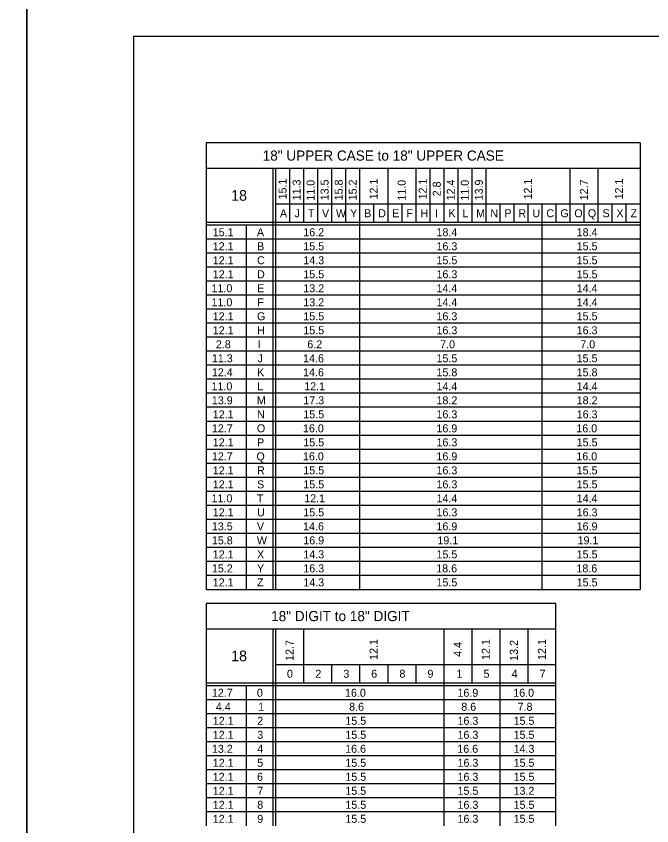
# Model space of a CAD drawing. Extents: x 637580 to 641849, y 297270 to 299646.
# Drawn here: x 640099.4 to 640337.4, y 298146.6 to 298450.1 of the extents above; entities that cross this region are included whole.
import ezdxf

# ---------------------------------------------------------------- set-up
doc = ezdxf.new("R2010")
doc.units = 0
for name, color, linetype in [('1', 7, 'Continuous'), ('2', 7, 'Continuous'), ('XCS-GRID-HVGL', 7, 'Continuous')]:
    doc.layers.add(name, color=color, linetype=linetype)

msp = doc.modelspace()

# ---------------------------------------------------------------- linework, layer by layer
at = {"layer": '1'}
for q in [(640929.31, 298442.63), (640143.31, 297878.63)]:
    msp.add_line((640143.31, 298442.63), q, dxfattribs=at)
at = {"layer": '2'}
for p, q in [((640333.01, 298402.63), (640170.51, 298402.63)), ((640170.51, 298402.63), (640170.51, 298235.25)), ((640333.01, 298402.63), (640333.01, 298235.25)), ((640170.51, 298393.13), (640333.01, 298393.13)), ((640195.51, 298393.13), (640195.51, 298235.25)), ((640196.51, 298393.13), (640196.51, 298235.25)), ((640201.76, 298393.13), (640201.76, 298372.75)), ((640207.01, 298393.13), (640207.01, 298372.75)), ((640212.26, 298393.13), (640212.26, 298372.75)), ((640217.51, 298393.13), (640217.51, 298372.75)), ((640222.76, 298393.13), (640222.76, 298372.75)), ((640228.01, 298393.13), (640228.01, 298235.25)), ((640238.51, 298393.13), (640238.51, 298372.75)), ((640249.01, 298393.13), (640249.01, 298372.75)), ((640254.26, 298393.13), (640254.26, 298372.75)), ((640259.51, 298393.13), (640259.51, 298372.75)), ((640264.76, 298393.13), (640264.76, 298372.75)), ((640270.01, 298393.13), (640270.01, 298372.75)), ((640275.26, 298393.13), (640275.26, 298372.75)), ((640306.76, 298393.13), (640306.76, 298372.75)), ((640317.26, 298393.13), (640317.26, 298372.75)), ((640196.51, 298379.75), (640333.01, 298379.75)), ((640233.26, 298379.75), (640233.26, 298372.75)), ((640243.76, 298379.75), (640243.76, 298372.75)), ((640280.51, 298379.75), (640280.51, 298372.75)), ((640285.76, 298379.75), (640285.76, 298372.75)), ((640291.01, 298379.75), (640291.01, 298372.75)), ((640291.01, 298379.75), (640291.01, 298372.75)), ((640296.26, 298379.75), (640296.26, 298235.25)), ((640301.51, 298379.75), (640301.51, 298372.75)), ((640312.01, 298379.75), (640312.01, 298372.75)), ((640322.51, 298379.75), (640322.51, 298372.75)), ((640327.76, 298379.75), (640327.76, 298372.75)), ((640333.01, 298372.75), (640170.51, 298372.75)), ((640333.01, 298371.75), (640170.51, 298371.75)), ((640185.51, 298371.75), (640185.51, 298235.25)), ((640333.01, 298366.5), (640170.51, 298366.5)), ((640333.01, 298361.25), (640170.51, 298361.25)), ((640333.01, 298356), (640170.51, 298356)), ((640333.01, 298350.75), (640170.51, 298350.75)), ((640333.01, 298345.5), (640170.51, 298345.5)), ((640333.01, 298340.25), (640170.51, 298340.25)), ((640333.01, 298335), (640170.51, 298335)), ((640333.01, 298329.75), (640170.51, 298329.75)), ((640333.01, 298324.5), (640170.51, 298324.5)), ((640333.01, 298319.25), (640170.51, 298319.25)), ((640333.01, 298314), (640170.51, 298314)), ((640333.01, 298308.75), (640170.51, 298308.75)), ((640333.01, 298303.5), (640170.51, 298303.5)), ((640333.01, 298298.25), (640170.51, 298298.25)), ((640333.01, 298293), (640170.51, 298293)), ((640333.01, 298287.75), (640170.51, 298287.75)), ((640333.01, 298282.5), (640170.51, 298282.5)), ((640333.01, 298277.25), (640170.51, 298277.25)), ((640333.01, 298272), (640170.51, 298272)), ((640333.01, 298266.75), (640170.51, 298266.75)), ((640333.01, 298261.5), (640170.51, 298261.5)), ((640333.01, 298256.25), (640170.51, 298256.25)), ((640333.01, 298251), (640170.51, 298251)), ((640333.01, 298245.75), (640170.51, 298245.75)), ((640333.01, 298240.5), (640170.51, 298240.5)), ((640170.51, 298235.25), (640170.51, 298235.25)), ((640170.51, 298235.25), (640333.01, 298235.25)), ((640301.51, 298230), (640170.51, 298230)), ((640170.51, 298230), (640170.51, 298146.63)), ((640301.51, 298146.63), (640301.51, 298230)), ((640170.51, 298220.5), (640301.51, 298220.5)), ((640195.51, 298220.5), (640195.51, 298146.63)), ((640196.51, 298220.5), (640196.51, 298146.63)), ((640207.01, 298220.5), (640207.01, 298200.13)), ((640259.51, 298220.5), (640259.51, 298146.63)), ((640270.01, 298220.5), (640270.01, 298200.13)), ((640280.51, 298220.5), (640280.51, 298146.63)), ((640291.01, 298220.5), (640291.01, 298200.13)), ((640196.51, 298207.13), (640301.51, 298207.13)), ((640217.51, 298207.13), (640217.51, 298200.13)), ((640228.01, 298207.13), (640228.01, 298200.13)), ((640238.51, 298207.13), (640238.51, 298200.13)), ((640249.01, 298207.13), (640249.01, 298200.13)), ((640301.51, 298200.13), (640170.51, 298200.13)), ((640301.51, 298199.13), (640170.51, 298199.13)), ((640185.51, 298199.13), (640185.51, 298146.63)), ((640301.51, 298193.88), (640170.51, 298193.88)), ((640301.51, 298188.63), (640170.51, 298188.63)), ((640301.51, 298183.38), (640170.51, 298183.38)), ((640301.51, 298178.13), (640170.51, 298178.13)), ((640301.51, 298172.88), (640170.51, 298172.88)), ((640301.51, 298167.63), (640170.51, 298167.63)), ((640301.51, 298162.38), (640170.51, 298162.38)), ((640301.51, 298157.13), (640170.51, 298157.13)), ((640301.51, 298151.88), (640170.51, 298151.88))]:
    msp.add_line(p, q, dxfattribs=at)
at = {"layer": 'XCS-GRID-HVGL'}
for points in [[(639262.31, 298457.63), (640103.31, 298457.63), (640103.31, 297863.63), (639262.31, 297863.63)], [(640103.31, 298457.63), (640944.31, 298457.63), (640944.31, 297863.63), (640103.31, 297863.63)]]:
    msp.add_lwpolyline(points, close=True, dxfattribs=at)

# ---------------------------------------------------------------- texts
at = {"layer": '2'}
for s, height, p in [('18" UPPER CASE to 18" UPPER CASE', 3.8, (640191.7, 298395.98)), ('18', 4, (640179.88, 298380.94)), ('A', 3, (640198.16, 298374.75)), ('J', 3, (640203.64, 298374.75)), ('T', 3, (640208.64, 298374.75)), ('V', 3, (640213.91, 298374.75)), ('W', 3, (640219.13, 298374.75)), ('Y', 3, (640224.44, 298374.75)), ('B', 3, (640229.7, 298374.75)), ('D', 3, (640234.95, 298374.75)), ('E', 3, (640240.22, 298374.75)), ('F', 3, (640245.52, 298374.75)), ('H', 3, (640250.79, 298374.75)), ('I', 3, (640256.2, 298374.75)), ('K', 3, (640261.29, 298374.75)), ('L', 3, (640266.54, 298374.75)), ('M', 3, (640271.63, 298374.75)), ('N', 3, (640276.95, 298374.75)), ('P', 3, (640282.2, 298374.75)), ('R', 3, (640287.45, 298374.75)), ('U', 3, (640292.69, 298374.75)), ('C', 3, (640297.95, 298374.75)), ('G', 3, (640303.2, 298374.75)), ('O', 3, (640308.41, 298374.75)), ('Q', 3, (640313.48, 298374.75)), ('S', 3, (640318.97, 298374.75)), ('X', 3, (640324.19, 298374.75)), ('Z', 3, (640329.45, 298374.75)), ('15.1', 3, (640173, 298367.63)), ('A', 3, (640189.53, 298367.63)), ('16.2', 3, (640206.91, 298367.63)), ('18.4', 3, (640256.79, 298367.63)), ('18.4', 3, (640309.29, 298367.63)), ('12.1', 3, (640173, 298362.38)), ('B', 3, (640189.58, 298362.38)), ('15.5', 3, (640206.91, 298362.38)), ('16.3', 3, (640256.79, 298362.38)), ('15.5', 3, (640309.29, 298362.38)), ('12.1', 3, (640173, 298357.13)), ('C', 3, (640189.58, 298357.13)), ('14.3', 3, (640206.91, 298357.13)), ('15.5', 3, (640256.79, 298357.13)), ('15.5', 3, (640309.29, 298357.13)), ('12.1', 3, (640173, 298351.88)), ('D', 3, (640189.58, 298351.88)), ('15.5', 3, (640206.91, 298351.88)), ('16.3', 3, (640256.79, 298351.88)), ('15.5', 3, (640309.29, 298351.88)), ('11.0', 3, (640172.53, 298346.63)), ('E', 3, (640189.59, 298346.63)), ('13.2', 3, (640206.91, 298346.63)), ('14.4', 3, (640256.79, 298346.63)), ('14.4', 3, (640309.29, 298346.63)), ('11.0', 3, (640172.53, 298341.38)), ('F', 3, (640189.65, 298341.38)), ('13.2', 3, (640206.91, 298341.38)), ('14.4', 3, (640256.79, 298341.38)), ('14.4', 3, (640309.29, 298341.38)), ('12.1', 3, (640173, 298336.13)), ('G', 3, (640189.58, 298336.13)), ('15.5', 3, (640206.91, 298336.13)), ('16.3', 3, (640256.79, 298336.13)), ('15.5', 3, (640309.29, 298336.13)), ('12.1', 3, (640173, 298330.88)), ('H', 3, (640189.66, 298330.88)), ('15.5', 3, (640206.91, 298330.88)), ('16.3', 3, (640256.79, 298330.88)), ('16.3', 3, (640309.29, 298330.88)), ('2.8', 3, (640174.16, 298325.63)), ('I', 3, (640189.83, 298325.63)), ('6.2', 3, (640208.41, 298325.63)), ('7.0', 3, (640258.16, 298325.63)), ('7.0', 3, (640310.66, 298325.63)), ('11.3', 3, (640172.66, 298320.38)), ('J', 3, (640189.77, 298320.38)), ('14.6', 3, (640206.83, 298320.38)), ('15.5', 3, (640256.79, 298320.38)), ('15.5', 3, (640309.29, 298320.38)), ('12.4', 3, (640172.66, 298315.13)), ('K', 3, (640189.66, 298315.13)), ('14.6', 3, (640206.83, 298315.13)), ('15.8', 3, (640256.79, 298315.13)), ('15.8', 3, (640309.29, 298315.13)), ('11.0', 3, (640172.53, 298309.88)), ('L', 3, (640189.66, 298309.88)), ('12.1', 3, (640207.25, 298309.88)), ('14.4', 3, (640256.79, 298309.88)), ('14.4', 3, (640309.29, 298309.88)), ('13.9', 3, (640172.65, 298304.63)), ('M', 3, (640189.51, 298304.63)), ('17.3', 3, (640206.91, 298304.63)), ('18.2', 3, (640256.79, 298304.63)), ('18.2', 3, (640309.29, 298304.63)), ('12.1', 3, (640173, 298299.38)), ('N', 3, (640189.58, 298299.38)), ('15.5', 3, (640206.91, 298299.38)), ('16.3', 3, (640256.79, 298299.38)), ('16.3', 3, (640309.29, 298299.38)), ('12.7', 3, (640172.66, 298294.13)), ('O', 3, (640189.53, 298294.13)), ('16.0', 3, (640206.78, 298294.13)), ('16.9', 3, (640256.77, 298294.13)), ('16.0', 3, (640309.16, 298294.13)), ('12.1', 3, (640173, 298288.88)), ('P', 3, (640189.58, 298288.88)), ('15.5', 3, (640206.91, 298288.88)), ('16.3', 3, (640256.79, 298288.88)), ('15.5', 3, (640309.29, 298288.88)), ('12.7', 3, (640172.66, 298283.63)), ('Q', 3, (640189.35, 298283.63)), ('16.0', 3, (640206.78, 298283.63)), ('16.9', 3, (640256.77, 298283.63)), ('16.0', 3, (640309.16, 298283.63)), ('12.1', 3, (640173, 298278.38)), ('R', 3, (640189.58, 298278.38)), ('15.5', 3, (640206.91, 298278.38)), ('16.3', 3, (640256.79, 298278.38)), ('15.5', 3, (640309.29, 298278.38)), ('12.1', 3, (640173, 298273.13)), ('S', 3, (640189.59, 298273.13)), ('15.5', 3, (640206.91, 298273.13)), ('16.3', 3, (640256.79, 298273.13)), ('15.5', 3, (640309.29, 298273.13)), ('11.0', 3, (640172.53, 298267.88)), ('T', 3, (640189.52, 298267.88)), ('12.1', 3, (640207.25, 298267.88)), ('14.4', 3, (640256.79, 298267.88)), ('14.4', 3, (640309.29, 298267.88)), ('12.1', 3, (640173, 298262.63)), ('U', 3, (640189.57, 298262.63)), ('15.5', 3, (640206.91, 298262.63)), ('16.3', 3, (640256.79, 298262.63)), ('16.3', 3, (640309.29, 298262.63)), ('13.5', 3, (640172.66, 298257.38)), ('V', 3, (640189.53, 298257.38)), ('14.6', 3, (640206.83, 298257.38)), ('16.9', 3, (640256.77, 298257.38)), ('16.9', 3, (640309.27, 298257.38)), ('15.8', 3, (640172.66, 298252.13)), ('W', 3, (640189.51, 298252.13)), ('16.9', 3, (640206.9, 298252.13)), ('19.1', 3, (640257.13, 298252.13)), ('19.1', 3, (640309.63, 298252.13)), ('12.1', 3, (640173, 298246.88)), ('X', 3, (640189.57, 298246.88)), ('14.3', 3, (640206.91, 298246.88)), ('15.5', 3, (640256.79, 298246.88)), ('15.5', 3, (640309.29, 298246.88)), ('15.2', 3, (640172.66, 298241.63)), ('Y', 3, (640189.57, 298241.63)), ('16.3', 3, (640206.91, 298241.63)), ('18.6', 3, (640256.7, 298241.63)), ('18.6', 3, (640309.2, 298241.63)), ('12.1', 3, (640173, 298236.38)), ('Z', 3, (640189.58, 298236.38)), ('14.3', 3, (640206.91, 298236.38)), ('15.5', 3, (640256.79, 298236.38)), ('15.5', 3, (640309.29, 298236.38)), ('18" DIGIT to 18" DIGIT', 3.8, (640194.86, 298223.35)), ('18', 4, (640179.88, 298208.31)), ('0', 3, (640200.78, 298202.13)), ('2', 3, (640211.41, 298202.13)), ('3', 3, (640221.91, 298202.13)), ('6', 3, (640232.33, 298202.13)), ('8', 3, (640242.91, 298202.13)), ('9', 3, (640253.4, 298202.13)), ('1', 3, (640264.25, 298202.13)), ('5', 3, (640274.41, 298202.13)), ('4', 3, (640284.91, 298202.13)), ('7', 3, (640295.41, 298202.13)), ('12.7', 3, (640172.66, 298195)), ('0', 3, (640189.53, 298195)), ('16.0', 3, (640222.53, 298195)), ('16.9', 3, (640264.65, 298195)), ('16.0', 3, (640285.53, 298195)), ('4.4', 3, (640174.16, 298189.75)), ('1', 3, (640190, 298189.75)), ('8.6', 3, (640224.08, 298189.75)), ('8.6', 3, (640266.08, 298189.75)), ('7.8', 3, (640287.16, 298189.75)), ('12.1', 3, (640173, 298184.5)), ('2', 3, (640189.66, 298184.5)), ('15.5', 3, (640222.66, 298184.5)), ('16.3', 3, (640264.66, 298184.5)), ('15.5', 3, (640285.66, 298184.5)), ('12.1', 3, (640173, 298179.25)), ('3', 3, (640189.66, 298179.25)), ('15.5', 3, (640222.66, 298179.25)), ('16.3', 3, (640264.66, 298179.25)), ('15.5', 3, (640285.66, 298179.25)), ('13.2', 3, (640172.66, 298174)), ('4', 3, (640189.66, 298174)), ('16.6', 3, (640222.58, 298174)), ('16.6', 3, (640264.58, 298174)), ('14.3', 3, (640285.66, 298174)), ('12.1', 3, (640173, 298168.75)), ('5', 3, (640189.66, 298168.75)), ('15.5', 3, (640222.66, 298168.75)), ('16.3', 3, (640264.66, 298168.75)), ('15.5', 3, (640285.66, 298168.75)), ('12.1', 3, (640173, 298163.5)), ('6', 3, (640189.58, 298163.5)), ('15.5', 3, (640222.66, 298163.5)), ('16.3', 3, (640264.66, 298163.5)), ('15.5', 3, (640285.66, 298163.5)), ('12.1', 3, (640173, 298158.25)), ('7', 3, (640189.66, 298158.25)), ('15.5', 3, (640222.66, 298158.25)), ('15.5', 3, (640264.66, 298158.25)), ('13.2', 3, (640285.66, 298158.25)), ('12.1', 3, (640173, 298153)), ('8', 3, (640189.66, 298153)), ('15.5', 3, (640222.66, 298153)), ('16.3', 3, (640264.66, 298153)), ('15.5', 3, (640285.66, 298153)), ('12.1', 3, (640173, 298147.75)), ('9', 3, (640189.65, 298147.75)), ('15.5', 3, (640222.66, 298147.75)), ('16.3', 3, (640264.66, 298147.75)), ('15.5', 3, (640285.66, 298147.75))]:
    msp.add_text(s, height=height, dxfattribs=at).set_placement(p)
for s, p in [('15.1', (640200.64, 298381.43)), ('11.3', (640205.89, 298381.09)), ('11.0', (640211.14, 298380.96)), ('13.5', (640216.39, 298381.09)), ('15.8', (640221.64, 298381.09)), ('15.2', (640226.89, 298381.09)), ('12.1', (640234.76, 298381.43)), ('11.0', (640245.26, 298380.96)), ('12.1', (640253.14, 298381.43)), ('2.8', (640258.39, 298382.59)), ('12.4', (640263.64, 298381.09)), ('11.0', (640268.89, 298380.96)), ('13.9', (640274.14, 298381.08)), ('12.1', (640292.51, 298381.43)), ('12.7', (640313.51, 298381.09)), ('12.1', (640326.64, 298381.43)), ('12.1', (640234.76, 298208.81)), ('12.1', (640276.76, 298208.81)), ('12.1', (640297.76, 298208.81)), ('12.7', (640203.26, 298208.46)), ('4.4', (640266.26, 298209.96)), ('13.2', (640287.26, 298208.46))]:
    msp.add_text(s, height=3, rotation=90, dxfattribs=at).set_placement(p)

doc.saveas('drawing.dxf')
